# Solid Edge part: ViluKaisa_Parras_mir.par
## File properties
Author: kaisa
Template: Iso Metric Part.par
Last saved by: kaisa
Revision: 8
Application: Solid Edge
Density: 7750.000 kg/m^3
Accuracy: 0.990
Username: kaisa
Material: Stainless steel
Face Style: Teal
Fill Style: ANSI32(Steel)
Virtual Style: ANSI32(Steel)
Grouping: Metals\Steel
LibraryName: Materials
Coef. of Thermal Exp: 1.6e-05
Thermal Conductivity: 17.0
Specific Heat: 502.0
Modulus of Elasticity: 193053196000.0
Poisson's Ratio: 0.29
Yield Stress: 310264065.0
Ultimate Stress: 641212401.0
Elongation: 0.0
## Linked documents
ViluKaisa_Parras.par
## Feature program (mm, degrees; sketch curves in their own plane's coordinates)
part copy "CopiedPart_1"
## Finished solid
Body 1: solid body, 30 faces, 44 edges, 16 vertices.
  Faces by surface: plane 15, cylinder 10, offset 2, swept 2, spline 1
  Edges by curve: circle 20, line 10, intersection 6, spline 6, curve on surface 2
Bounding box of the edges (mm; curved faces can reach further): 279.950 x 90.000 x 50.582, from (-139.9748, -10, 5.9842) to (139.9748, 80, 56.5662).
Cylindrical faces by radius (mm): R1 x8, R3 x2
Planar faces by outward normal: +z 3, -y 2, -z 1, oblique 9
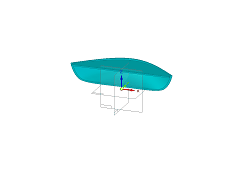
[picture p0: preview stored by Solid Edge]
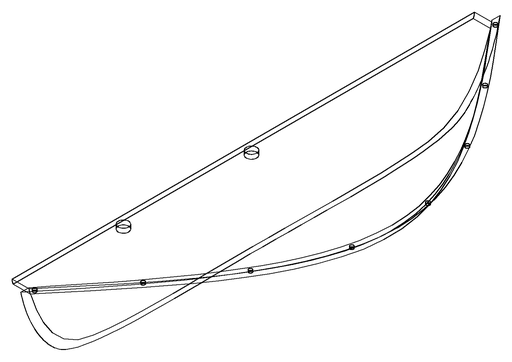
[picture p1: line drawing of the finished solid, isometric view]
